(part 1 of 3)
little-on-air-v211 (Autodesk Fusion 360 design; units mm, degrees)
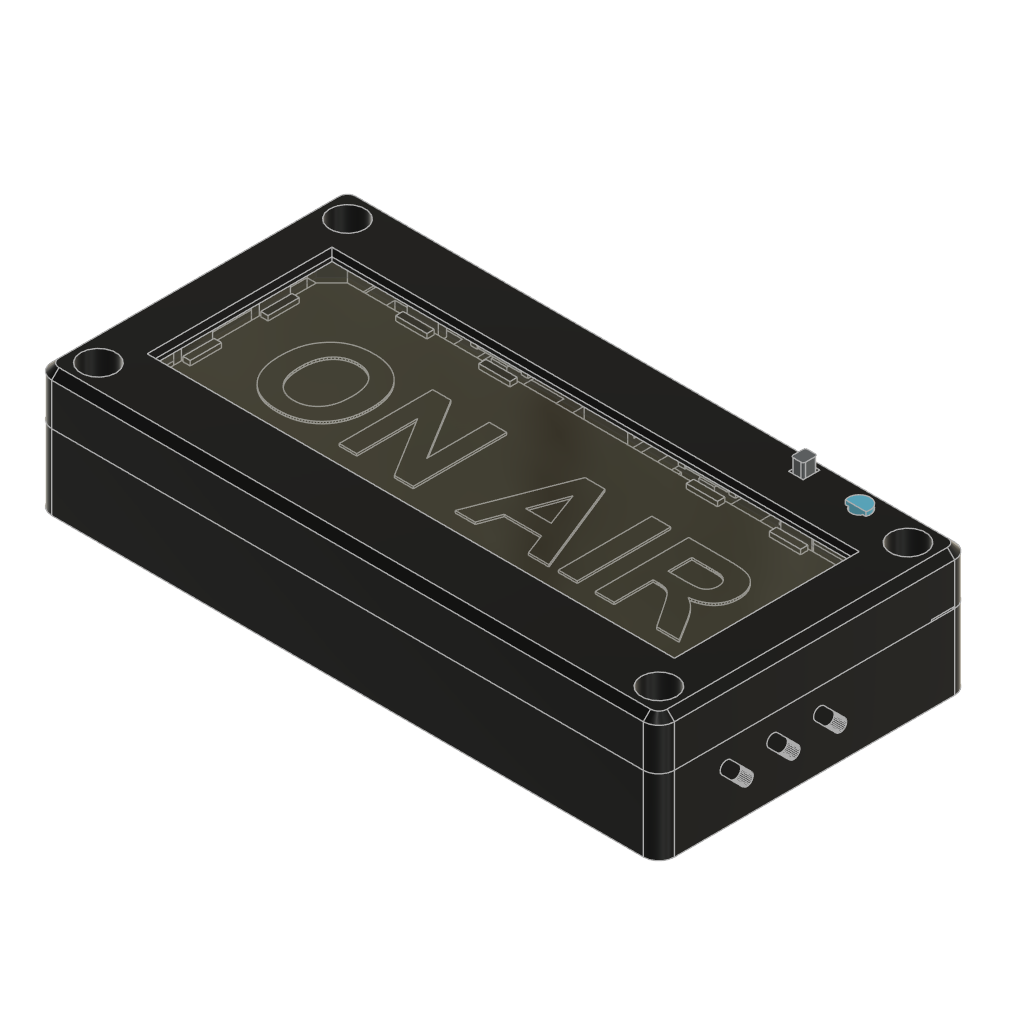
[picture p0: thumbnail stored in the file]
description: netfabb.mesh_body
description: Laser only; rear-engrave mirrored shared vector master
description: 1.6 mm black; 0.4 mm white letters; integral hidden spacer pads
description: Flat frame down, LED pads up; no electronics mounts
description: Optional 1.6 mm laminate only; omit with printed backing; print 0.1 mm layers
description: 8x8x2; emitter offset assumed 1 mm
description: Measured 28.1 x17.5; USB overhang 1.3; PCB thickness and USB section provisional
description: Measured body 10.6 x6 x5.05; flange 19.73; terminals 2.6
description: Measured 2.95 square, 5 high; 5.8 slot gives 2.85 mm travel
description: 9.1 x3.72 x3.36; 0.7 mm terminals, 1.85 mm clear gaps, symmetric rows
description: 1.5 square x1.87; full travel 2.4 mm
description: Measured 17.8 x21 x1.2; USB centered across width, 1.75 overhang
description: 24 mm total case; parallel PCB nests; back face on print bed
description: Flat PCB keeper; broad rails, short contact pads, keyed reset guide
description: 52 x21 x10, front clearance preserved; no wire bundles on pouch
description: Existing inline 680 uF; laid on its side, maximum 8 dia x11.5 body
description: Eight identical M3x8 button heads, maximum 5.7 diameter x1.65 height
description: Ordinary M3 nuts, 5.5 across flats x2.4 thick
parameter "case_w" = 120 comment "Front width"
parameter "case_h" = 60 comment "Front height"
parameter "case_d" = 24 comment "Rear wiring margin included"
parameter "wall" = 2.4 comment "Structural shell wall"
parameter "front_lip" = 1.6 comment "Front optical lip"
parameter "front_depth" = 9.5 comment "Main front/rear seam"
parameter "acrylic_t" = 3.175 comment "Nominal Amazon 1/8 inch; measure actual sheet"
parameter "panel_w" = 104 comment "Shared optical outline"
parameter "panel_h" = 38 comment "Shared optical outline"
parameter "air_gap" = 0.5 comment "Rear engraving to white letter tips"
parameter "backing_base" = 1.6 comment "Black printed base"
parameter "letter_relief" = 0.4 comment "White letters above black base"
parameter "tray_t" = 1.6 comment "Optical retainer thickness"
parameter "fit" = 0.25 comment "Nominal mating clearance per side"
parameter "m3_hole" = 3.6 comment "M3 clearance"
parameter "nut_af" = 6 comment "Ordinary M3 nut trap"
parameter "head_d" = 6.8 comment "M3 socket-head counterbore"
parameter "head_depth" = 3.2 comment "Front bearing plane"
parameter "led_w" = 8 comment "Separated LED module"
parameter "led_h" = 8 comment "Separated LED module"
parameter "led_t" = 2 comment "LED module thickness"
parameter "led_optical_offset" = 1 comment "Unmeasured emitter center from module front"
parameter "text_h" = 18 comment "Reference text height"
parameter "switch_w" = 9.1
parameter "switch_h" = 3.72
parameter "switch_t" = 3.36
parameter "switch_throw" = 2.4
parameter "actuator_w" = 1.5
parameter "actuator_d" = 1.5
parameter "actuator_h" = 1.87
parameter "reset_y" = 56 comment "Provisional XIAO reset center"
parameter "reset_depth" = 14.55 comment "Provisional XIAO reset center"
parameter "reset_tip_x" = 110.7 comment "v2.5 measured reset stack and exterior projection"
parameter "reset_stroke" = 0.4 comment "v2.5 measured reset stack and exterior projection"
parameter "spdt_body_length" = 10.6
parameter "spdt_body_depth" = 6
parameter "spdt_body_height" = 5.05
parameter "spdt_flange_length" = 19.73
parameter "spdt_knob_height" = 5
parameter "spdt_knob_envelope" = 2.95
parameter "spdt_travel" = 2.85
parameter "spdt_fit_clearance" = 0.2
parameter "charger_pcb_width" = 17.5 comment "v2.3 measured fit revision; see change record"
parameter "charger_pcb_length" = 28.1 comment "v2.3 measured fit revision; see change record"
parameter "charger_usb_overhang" = 1.25 comment "v2.3 measured fit revision; see change record"
parameter "charger_fit_per_side" = 0.3 comment "v2.3 measured fit revision; see change record"
parameter "reset_guide_length" = 4 comment "v2.3 measured fit revision; see change record"
parameter "reset_guide_per_side" = 0.2 comment "v2.3 measured fit revision; see change record"
parameter "xiao_shift_side" = -0.2 comment "v2.3 measured fit revision; see change record"
parameter "xiao_shift_top" = 1.3 comment "v2.3 measured fit revision; see change record"
parameter "dpdt_actuator_exposed" = 0.72 comment "v2.3 measured fit revision; see change record"
parameter "charger_usb_width" = 8.85 comment "User measured September 10, 2026"
parameter "charger_usb_height" = 3.1 comment "User measured September 10, 2026"
parameter "xiao_usb_width" = 8.97 comment "User measured September 10, 2026"
parameter "xiao_usb_height" = 3.17 comment "User measured September 10, 2026"
parameter "xiao_usb_overhang" = 1.75 comment "User measured September 10, 2026"
parameter "dpdt_fit_per_side" = 0.35 comment "v2.4 second physical-fit revision"
parameter "yoke_main_thickness" = 2.75 comment "v2.4 second physical-fit revision"
parameter "side_vent_length" = 8 comment "v2.4 second physical-fit revision"
parameter "side_vent_width" = 2.4 comment "v2.4 second physical-fit revision"
parameter "xiao_pcb_thickness" = 1.2 comment "v2.5 measured physical fit"
parameter "xiao_usb_edge_margin" = 4.415 comment "v2.5 measured physical fit"
parameter "xiao_usb_front_depth" = 15.965 comment "v2.5 measured physical fit"
parameter "dpdt_terminal_width" = 0.7 comment "v2.5 measured physical fit"
parameter "dpdt_terminal_clear_gap" = 1.85 comment "v2.5 measured physical fit"
parameter "charger_lower_support_from_end" = 5 comment "v2.5 measured physical fit"
parameter "reset_free_play" = 0.1 comment "v2.5 measured reset stack"
parameter "reset_exterior_projection" = 3 comment "v2.5 measured reset stack"
parameter "reset_target_from_pcb_back" = 1.8 comment "v2.5 measured reset stack"
parameter "yoke_front_depth" = 9.65 comment "v2.5 common flat print face; no support for POWER roof"
parameter "yoke_screw_seat_thickness" = 1.75 comment "v2.5 common flat print face; no support for POWER roof"
parameter "common_screw_length" = 8 comment "v2.6 service revision"
parameter "closure_head_bearing" = 6.6 comment "v2.6 service revision"
parameter "closure_nut_front" = 11.5 comment "v2.6 service revision"
parameter "xiao_inward_shift" = 2 comment "v2.6 service revision"
parameter "xiao_rgb_y" = 55.006 comment "v2.6 service revision"
parameter "xiao_rgb_depth" = 26.155 comment "v2.6 service revision"
parameter "dpdt_pocket_width" = 9.5 comment "v2.6 service revision"
parameter "dpdt_retained_gap" = 0.15 comment "v2.6 service revision"
parameter "closure_nut_roof" = 2 comment "v2.6 full-depth common screw nut roof"
parameter "xiao_flat_pcb_back" = 19.7 comment "v2.7 measured component layout"
parameter "charger_flat_pcb_back" = 15.3 comment "v2.7 measured component layout"
parameter "reset_front_freeplay" = 0.25 comment "v2.7 measured component layout"
parameter "reset_front_stroke" = 0.8 comment "v2.7 measured component layout"
parameter "reset_front_projection" = 2.5 comment "v2.7 measured component layout"
parameter "indicator_guide_diameter" = 3.05
parameter "front_outer_bevel" = 1.4 comment "Equal-distance 45 degree cosmetic front chamfer"
parameter "front_opening_bevel" = 0.8 comment "Equal-distance 45 degree cosmetic front chamfer"
base_feature "Base Feature1" bodies "Body1"
base_feature "Base Feature1" bodies "Body1"
base_feature "Base Feature1"
base_feature "Base Feature1" bodies "Body1"
base_feature "Base Feature1" bodies "Body1"
base_feature "Base Feature1" bodies "Body1"
base_feature "Base Feature1" bodies "LED module", "LED module (1)", "LED module (2)", "LED module (3)"
base_feature "Base Feature1" bodies "Charger PCB", "Charger IC envelope", "Measured USB-C socket envelope"
base_feature "Base Feature1" bodies "SPDT main body"
base_feature "Base Feature1" bodies "SPDT lever"
base_feature "Base Feature1" bodies "Measured DPDT body"
base_feature "Base Feature1" bodies "Direct MODE actuator"
base_feature "Base Feature1" bodies "XIAO PCB", "XIAO component envelope", "Measured centered USB-C socket"
move "Move1"
move "Move1"
move "Move1"
move "Move1"
move "Move1"
move "Move1"
sketch "Close obsolete upper-right screw opening profile" plane through (0, 0, 0) normal (0, 0, 1) x axis (1, 0, 0)
  circle C1 centre (96, 54) radius 3.405
  dimension "d86" diameter C1 = 6.81
extrude "Extrude1" new body sketch "Close obsolete upper-right screw opening profile" against normal blind 9.5 bodies "Close obsolete upper-right screw opening"
combine "Combine1" bodies "Close obsolete upper-right screw opening"
work_plane "WorkPlane1" AlongDistance -1.6 ExtraOffset 0
sketch "Remove obsolete inboard compression seat profile" plane through (0, 0, -1.6) normal (0, 0, 1) x axis (1, 0, 0)
  line L1 (100.21, 49.79) -> (91.79, 49.79)
  line L2 (100.21, 57.6) -> (100.21, 49.79)
  line L3 (91.79, 57.6) -> (100.21, 57.6)
  line L4 (91.79, 49.79) -> (91.79, 57.6)
  point P2 (91.79, 49.79)
  point P3 (100.21, 49.79)
  point P4 (100.21, 57.6)
  dimension "d91" distance P2 P3 = 8.42
  dimension "d92" distance P3 P4 = 7.81
extrude "Extrude2" cut sketch "Remove obsolete inboard compression seat profile" against normal blind 7.91
work_plane "WorkPlane2" AlongDistance -1.5 ExtraOffset 0
sketch "New upper-right corner compression seat profile" plane through (0, 0, -1.5) normal (0, 0, 1) x axis (1, 0, 0)
  line L1 (118.2, 49.8) -> (109.8, 49.8)
  line L2 (118.2, 58.2) -> (118.2, 49.8)
  line L3 (109.8, 58.2) -> (118.2, 58.2)
  line L4 (109.8, 49.8) -> (109.8, 58.2)
  point P2 (109.8, 49.8)
  point P3 (118.2, 49.8)
  point P4 (118.2, 58.2)
  dimension "d97" distance P2 P3 = 8.4
  dimension "d98" distance P3 P4 = 8.4
extrude "Extrude3" new body sketch "New upper-right corner compression seat profile" against normal blind 8 bodies "New upper-right corner compression seat"
combine "Combine2" bodies "New upper-right corner compression seat"
work_plane "WorkPlane3" AlongDistance 0.02 ExtraOffset 0
sketch "New common M3 clearance profile" plane through (0, 0, 0.02) normal (0, 0, 1) x axis (1, 0, 0)
  circle C1 centre (114, 54) radius 1.8
  dimension "d103" diameter C1 = 3.6
extrude "Extrude4" cut sketch "New common M3 clearance profile" against normal blind 9.54
work_plane "WorkPlane4" AlongDistance 0.02 ExtraOffset 0
sketch "New common inset head bearing profile" plane through (0, 0, 0.02) normal (0, 0, 1) x axis (1, 0, 0)
  circle C1 centre (114, 54) radius 3.4
  dimension "d108" diameter C1 = 6.8
extrude "Extrude5" cut sketch "New common inset head bearing profile" against normal blind 6.62
work_plane "WorkPlane5" AlongDistance -1.5 ExtraOffset 0
sketch "Front reset guide broad collar profile" plane through (0, 0, -1.5) normal (0, 0, 1) x axis (1, 0, 0)
  line L1 (95.515, 52.6) -> (88.515, 52.6)
  line L2 (95.515, 59.4) -> (95.515, 52.6)
  line L3 (88.515, 59.4) -> (95.515, 59.4)
  line L4 (88.515, 52.6) -> (88.515, 59.4)
  point P2 (88.515, 52.6)
  point P3 (95.515, 52.6)
  point P4 (95.515, 59.4)
  dimension "d113" distance P2 P3 = 7
  dimension "d114" distance P3 P4 = 6.8
extrude "Extrude6" new body sketch "Front reset guide broad collar profile" against normal blind 4.5 bodies "Front reset guide broad collar"
combine "Combine3" bodies "Front reset guide broad collar"
work_plane "WorkPlane6" AlongDistance 0.1 ExtraOffset 0
sketch "Front keyed reset running guide profile" plane through (0, 0, 0.1) normal (0, 0, 1) x axis (1, 0, 0)
  line L1 (93.415, 54.4) -> (90.615, 54.4)
  line L2 (93.415, 57.6) -> (93.415, 54.4)
  line L3 (90.615, 57.6) -> (93.415, 57.6)
  line L4 (90.615, 54.4) -> (90.615, 57.6)
  point P2 (90.615, 54.4)
  point P3 (93.415, 54.4)
  point P4 (93.415, 57.6)
  dimension "d119" distance P2 P3 = 2.8
  dimension "d120" distance P3 P4 = 3.2
extrude "Extrude7" cut sketch "Front keyed reset running guide profile" against normal blind 6.2
work_plane "WorkPlane7" AlongDistance -6 ExtraOffset 0
sketch "Reset captive flange loading pocket profile" plane through (0, 0, -6) normal (0, 0, 1) x axis (1, 0, 0)
  line L1 (94.915, 53.1) -> (89.115, 53.1)
  line L2 (94.915, 58.9) -> (94.915, 53.1)
  line L3 (89.115, 58.9) -> (94.915, 58.9)
  line L4 (89.115, 53.1) -> (89.115, 58.9)
  point P2 (89.115, 53.1)
  point P3 (94.915, 53.1)
  point P4 (94.915, 58.9)
  dimension "d125" distance P2 P3 = 5.8
  dimension "d126" distance P3 P4 = 5.8
extrude "Extrude8" cut sketch "Reset captive flange loading pocket profile" against normal blind 3.51
work_plane "WorkPlane8" AlongDistance 0.02 ExtraOffset 0
sketch "RGB6 front indicator aperture profile" plane through (0, 0, 0.02) normal (0, 0, 1) x axis (1, 0, 0)
  circle C1 centre (103.605, 55.006) radius 1.6
  dimension "d131" diameter C1 = 3.2
extrude "Extrude9" cut sketch "RGB6 front indicator aperture profile" + "Front reset guide broad collar profile" profile of S1:C1 blind -9.55
work_plane "WorkPlane1" AlongDistance -9.5 ExtraOffset 0
sketch "Slim rear envelope profile" plane through (0, 0, -9.5) normal (0, 0, 1) x axis (1, 0, 0)
  line L1 (117, 0) -> (3, 0)
  line L2 (120, 57) -> (120, 3)
  line L3 (3, 60) -> (117, 60)
  line L4 (0, 3) -> (0, 57)
  arc A1 centre (117, 3) radius 3 clockwise from (120, 3) to (117, 0)
  arc A2 centre (117, 57) radius 3 clockwise from (117, 60) to (120, 57)
  arc A3 centre (3, 57) radius 3 clockwise from (0, 57) to (3, 60)
  arc A4 centre (3, 3) radius 3 clockwise from (3, 0) to (0, 3)
extrude "Extrude1" new body sketch "Slim rear envelope profile" against normal blind 14.5
work_plane "WorkPlane2" AlongDistance -9.48 ExtraOffset 0
sketch "Open electronics cavity profile" plane through (0, 0, -9.48) normal (0, 0, 1) x axis (1, 0, 0)
  line L1 (117.6, 2.4) -> (2.4, 2.4)
  line L2 (117.6, 57.6) -> (117.6, 2.4)
  line L3 (2.4, 57.6) -> (117.6, 57.6)
  line L4 (2.4, 2.4) -> (2.4, 57.6)
  point P2 (2.4, 2.4)
  point P3 (117.6, 2.4)
  point P4 (117.6, 57.6)
  dimension "d140" distance P2 P3 = 115.2
  dimension "d141" distance P3 P4 = 55.2
extrude "Extrude2" cut sketch "Open electronics cavity profile" against normal blind 12.22
work_plane "WorkPlane3" AlongDistance -9.5 ExtraOffset 0
sketch "Closure boss profile" plane through (0, 0, -9.5) normal (0, 0, 1) x axis (1, 0, 0)
  line L1 (10.2, 1.8) -> (1.8, 1.8)
  line L2 (10.2, 10.2) -> (10.2, 1.8)
  line L3 (1.8, 10.2) -> (10.2, 10.2)
  line L4 (1.8, 1.8) -> (1.8, 10.2)
  point P2 (1.8, 1.8)
  point P3 (10.2, 1.8)
  point P4 (10.2, 10.2)
  dimension "d146" distance P2 P3 = 8.4
  dimension "d147" distance P3 P4 = 8.4
extrude "Extrude3" new body sketch "Closure boss profile" against normal blind 12.2 bodies "Closure boss"
combine "Combine1" bodies "Closure boss"
work_plane "WorkPlane4" AlongDistance -11.5 ExtraOffset 0
sketch "Closure boss nut flats" plane through (0, 0, -11.5) normal (0, 0, 1) x axis (1, 0, 0)
  line L1 (7.7321, 9) -> (9.4641, 6)
  line L2 (4.2679, 9) -> (7.7321, 9)
  line L3 (2.5359, 6) -> (4.2679, 9)
  line L4 (4.2679, 3) -> (2.5359, 6)
  line L5 (7.7321, 3) -> (4.2679, 3)
  line L6 (9.4641, 6) -> (7.7321, 3)
extrude "Extrude4" cut sketch "Closure boss nut flats" against normal blind 3
work_plane "WorkPlane5" AlongDistance -11.5 ExtraOffset 0
sketch "Closure boss inward nut mouth profile" plane through (0, 0, -11.5) normal (0, 0, 1) x axis (1, 0, 0)
  line L1 (10.5, 3) -> (6, 3)
  line L2 (10.5, 9) -> (10.5, 3)
  line L3 (6, 9) -> (10.5, 9)
  line L4 (6, 3) -> (6, 9)
  point P2 (6, 3)
  point P3 (10.5, 3)
  point P4 (10.5, 9)
  dimension "d156" distance P2 P3 = 4.5
  dimension "d157" distance P3 P4 = 6
extrude "Extrude5" cut sketch "Closure boss inward nut mouth profile" against normal blind 3
work_plane "WorkPlane6" AlongDistance -9.48 ExtraOffset 0
sketch "Closure boss blind M3 clearance profile" plane through (0, 0, -9.48) normal (0, 0, 1) x axis (1, 0, 0)
  circle C1 centre (6, 6) radius 1.8
  dimension "d162" diameter C1 = 3.6
extrude "Extrude6" cut sketch "Closure boss blind M3 clearance profile" against normal blind 5.72
work_plane "WorkPlane7" AlongDistance -9.5 ExtraOffset 0
sketch "Closure boss profile (1)" plane through (0, 0, -9.5) normal (0, 0, 1) x axis (1, 0, 0)
  line L1 (118.2, 1.8) -> (109.8, 1.8)
  line L2 (118.2, 10.2) -> (118.2, 1.8)
  line L3 (109.8, 10.2) -> (118.2, 10.2)
  line L4 (109.8, 1.8) -> (109.8, 10.2)
  point P2 (109.8, 1.8)
  point P3 (118.2, 1.8)
  point P4 (118.2, 10.2)
  dimension "d167" distance P2 P3 = 8.4
  dimension "d168" distance P3 P4 = 8.4
extrude "Extrude7" new body sketch "Closure boss profile (1)" against normal blind 12.2 bodies "Closure boss"
combine "Combine2" bodies "Closure boss"
work_plane "WorkPlane8" AlongDistance -11.5 ExtraOffset 0
sketch "Closure boss nut flats (1)" plane through (0, 0, -11.5) normal (0, 0, 1) x axis (1, 0, 0)
  line L1 (115.7321, 9) -> (117.4641, 6)
  line L2 (112.2679, 9) -> (115.7321, 9)
  line L3 (110.5359, 6) -> (112.2679, 9)
  line L4 (112.2679, 3) -> (110.5359, 6)
  line L5 (115.7321, 3) -> (112.2679, 3)
  line L6 (117.4641, 6) -> (115.7321, 3)
extrude "Extrude8" cut sketch "Closure boss nut flats (1)" against normal blind 3
work_plane "WorkPlane9" AlongDistance -11.5 ExtraOffset 0
sketch "Closure boss inward nut mouth profile (1)" plane through (0, 0, -11.5) normal (0, 0, 1) x axis (1, 0, 0)
  line L1 (114, 3) -> (109.5, 3)
  line L2 (114, 9) -> (114, 3)
  line L3 (109.5, 9) -> (114, 9)
  line L4 (109.5, 3) -> (109.5, 9)
  point P2 (109.5, 3)
  point P3 (114, 3)
  point P4 (114, 9)
  dimension "d177" distance P2 P3 = 4.5
  dimension "d178" distance P3 P4 = 6
extrude "Extrude9" cut sketch "Closure boss inward nut mouth profile (1)" against normal blind 3
work_plane "WorkPlane10" AlongDistance -9.48 ExtraOffset 0
sketch "Closure boss blind M3 clearance profile (1)" plane through (0, 0, -9.48) normal (0, 0, 1) x axis (1, 0, 0)
  circle C1 centre (114, 6) radius 1.8
  dimension "d183" diameter C1 = 3.6
extrude "Extrude10" cut sketch "Closure boss blind M3 clearance profile (1)" against normal blind 5.72
work_plane "WorkPlane11" AlongDistance -9.5 ExtraOffset 0
sketch "Closure boss profile (2)" plane through (0, 0, -9.5) normal (0, 0, 1) x axis (1, 0, 0)
  line L1 (10.2, 49.8) -> (1.8, 49.8)
  line L2 (10.2, 58.2) -> (10.2, 49.8)
  line L3 (1.8, 58.2) -> (10.2, 58.2)
  line L4 (1.8, 49.8) -> (1.8, 58.2)
  point P2 (1.8, 49.8)
  point P3 (10.2, 49.8)
  point P4 (10.2, 58.2)
  dimension "d188" distance P2 P3 = 8.4
  dimension "d189" distance P3 P4 = 8.4
extrude "Extrude11" new body sketch "Closure boss profile (2)" against normal blind 12.2 bodies "Closure boss"
combine "Combine3" bodies "Closure boss"
work_plane "WorkPlane12" AlongDistance -11.5 ExtraOffset 0
sketch "Closure boss nut flats (2)" plane through (0, 0, -11.5) normal (0, 0, 1) x axis (1, 0, 0)
  line L1 (3, 55.7321) -> (6, 57.4641)
  line L2 (3, 52.2679) -> (3, 55.7321)
  line L3 (6, 50.5359) -> (3, 52.2679)
  line L4 (9, 52.2679) -> (6, 50.5359)
  line L5 (9, 55.7321) -> (9, 52.2679)
  line L6 (6, 57.4641) -> (9, 55.7321)
extrude "Extrude12" cut sketch "Closure boss nut flats (2)" against normal blind 3
work_plane "WorkPlane13" AlongDistance -11.5 ExtraOffset 0
sketch "Closure boss inward nut mouth profile (2)" plane through (0, 0, -11.5) normal (0, 0, 1) x axis (1, 0, 0)
  line L1 (9, 49.5) -> (3, 49.5)
  line L2 (9, 54) -> (9, 49.5)
  line L3 (3, 54) -> (9, 54)
  line L4 (3, 49.5) -> (3, 54)
  point P2 (3, 49.5)
  point P3 (9, 49.5)
  point P4 (9, 54)
  dimension "d198" distance P2 P3 = 6
  dimension "d199" distance P3 P4 = 4.5
extrude "Extrude13" cut sketch "Closure boss inward nut mouth profile (2)" against normal blind 3
work_plane "WorkPlane14" AlongDistance -9.48 ExtraOffset 0
sketch "Closure boss blind M3 clearance profile (2)" plane through (0, 0, -9.48) normal (0, 0, 1) x axis (1, 0, 0)
  circle C1 centre (6, 54) radius 1.8
  dimension "d204" diameter C1 = 3.6
extrude "Extrude14" cut sketch "Closure boss blind M3 clearance profile (2)" against normal blind 5.72
work_plane "WorkPlane15" AlongDistance -9.5 ExtraOffset 0
sketch "Closure boss profile (3)" plane through (0, 0, -9.5) normal (0, 0, 1) x axis (1, 0, 0)
  line L1 (118.2, 49.8) -> (109.8, 49.8)
  line L2 (118.2, 58.2) -> (118.2, 49.8)
  line L3 (109.8, 58.2) -> (118.2, 58.2)
  line L4 (109.8, 49.8) -> (109.8, 58.2)
  point P2 (109.8, 49.8)
  point P3 (118.2, 49.8)
  point P4 (118.2, 58.2)
  dimension "d209" distance P2 P3 = 8.4
  dimension "d210" distance P3 P4 = 8.4
extrude "Extrude15" new body sketch "Closure boss profile (3)" against normal blind 12.2 bodies "Closure boss"
combine "Combine4" bodies "Closure boss"
work_plane "WorkPlane16" AlongDistance -11.5 ExtraOffset 0
sketch "Closure boss nut flats (3)" plane through (0, 0, -11.5) normal (0, 0, 1) x axis (1, 0, 0)
  line L1 (115.7321, 57) -> (117.4641, 54)
  line L2 (112.2679, 57) -> (115.7321, 57)
  line L3 (110.5359, 54) -> (112.2679, 57)
  line L4 (112.2679, 51) -> (110.5359, 54)
  line L5 (115.7321, 51) -> (112.2679, 51)
  line L6 (117.4641, 54) -> (115.7321, 51)
extrude "Extrude16" cut sketch "Closure boss nut flats (3)" against normal blind 3
work_plane "WorkPlane17" AlongDistance -11.5 ExtraOffset 0
sketch "Closure boss inward nut mouth profile (3)" plane through (0, 0, -11.5) normal (0, 0, 1) x axis (1, 0, 0)
  line L1 (114, 51) -> (109.5, 51)
  line L2 (114, 57) -> (114, 51)
  line L3 (109.5, 57) -> (114, 57)
  line L4 (109.5, 51) -> (109.5, 57)
  point P2 (109.5, 51)
  point P3 (114, 51)
  point P4 (114, 57)
  dimension "d219" distance P2 P3 = 4.5
  dimension "d220" distance P3 P4 = 6
extrude "Extrude17" cut sketch "Closure boss inward nut mouth profile (3)" against normal blind 3
work_plane "WorkPlane18" AlongDistance -9.48 ExtraOffset 0
sketch "Closure boss blind M3 clearance profile (3)" plane through (0, 0, -9.48) normal (0, 0, 1) x axis (1, 0, 0)
  circle C1 centre (114, 54) radius 1.8
  dimension "d225" diameter C1 = 3.6
extrude "Extrude18" cut sketch "Closure boss blind M3 clearance profile (3)" against normal blind 5.72
work_plane "WorkPlane19" AlongDistance -12.4 ExtraOffset 0
sketch "Keeper boss profile" plane through (0, 0, -12.4) normal (0, 0, 1) x axis (1, 0, 0)
  line L1 (39.2, 33.8) -> (30.8, 33.8)
  line L2 (39.2, 42.2) -> (39.2, 33.8)
  line L3 (30.8, 42.2) -> (39.2, 42.2)
  line L4 (30.8, 33.8) -> (30.8, 42.2)
  point P2 (30.8, 33.8)
  point P3 (39.2, 33.8)
  point P4 (39.2, 42.2)
  dimension "d230" distance P2 P3 = 8.4
  dimension "d231" distance P3 P4 = 8.4
extrude "Extrude19" new body sketch "Keeper boss profile" against normal blind 9.3 bodies "Keeper boss"
combine "Combine5" bodies "Keeper boss"
work_plane "WorkPlane20" AlongDistance -13.8 ExtraOffset 0
sketch "Keeper boss nut flats" plane through (0, 0, -13.8) normal (0, 0, 1) x axis (1, 0, 0)
  line L1 (36.7321, 41) -> (38.4641, 38)
  line L2 (33.2679, 41) -> (36.7321, 41)
  line L3 (31.5359, 38) -> (33.2679, 41)
  line L4 (33.2679, 35) -> (31.5359, 38)
  line L5 (36.7321, 35) -> (33.2679, 35)
  line L6 (38.4641, 38) -> (36.7321, 35)
extrude "Extrude20" cut sketch "Keeper boss nut flats" against normal blind 3
work_plane "WorkPlane21" AlongDistance -13.8 ExtraOffset 0
sketch "Keeper boss inward nut mouth profile" plane through (0, 0, -13.8) normal (0, 0, 1) x axis (1, 0, 0)
  line L1 (39.5, 35) -> (35, 35)
  line L2 (39.5, 41) -> (39.5, 35)
  line L3 (35, 41) -> (39.5, 41)
  line L4 (35, 35) -> (35, 41)
  point P2 (35, 35)
  point P3 (39.5, 35)
  point P4 (39.5, 41)
  dimension "d240" distance P2 P3 = 4.5
  dimension "d241" distance P3 P4 = 6
extrude "Extrude21" cut sketch "Keeper boss inward nut mouth profile" against normal blind 3
work_plane "WorkPlane22" AlongDistance -12.38 ExtraOffset 0
sketch "Keeper boss blind M3 clearance profile" plane through (0, 0, -12.38) normal (0, 0, 1) x axis (1, 0, 0)
  circle C1 centre (35, 38) radius 1.8
  dimension "d246" diameter C1 = 3.6
extrude "Extrude22" cut sketch "Keeper boss blind M3 clearance profile" against normal blind 5.82
work_plane "WorkPlane23" AlongDistance -12.4 ExtraOffset 0
sketch "Keeper boss profile (1)" plane through (0, 0, -12.4) normal (0, 0, 1) x axis (1, 0, 0)
  line L1 (77.2, 33.8) -> (68.8, 33.8)
  line L2 (77.2, 42.2) -> (77.2, 33.8)
  line L3 (68.8, 42.2) -> (77.2, 42.2)
  line L4 (68.8, 33.8) -> (68.8, 42.2)
  point P2 (68.8, 33.8)
  point P3 (77.2, 33.8)
  point P4 (77.2, 42.2)
  dimension "d251" distance P2 P3 = 8.4
  dimension "d252" distance P3 P4 = 8.4
extrude "Extrude23" new body sketch "Keeper boss profile (1)" against normal blind 9.3 bodies "Keeper boss"
combine "Combine6" bodies "Keeper boss"
work_plane "WorkPlane24" AlongDistance -13.8 ExtraOffset 0
sketch "Keeper boss nut flats (1)" plane through (0, 0, -13.8) normal (0, 0, 1) x axis (1, 0, 0)
  line L1 (74.7321, 41) -> (76.4641, 38)
  line L2 (71.2679, 41) -> (74.7321, 41)
  line L3 (69.5359, 38) -> (71.2679, 41)
  line L4 (71.2679, 35) -> (69.5359, 38)
  line L5 (74.7321, 35) -> (71.2679, 35)
  line L6 (76.4641, 38) -> (74.7321, 35)
extrude "Extrude24" cut sketch "Keeper boss nut flats (1)" against normal blind 3
work_plane "WorkPlane25" AlongDistance -13.8 ExtraOffset 0
sketch "Keeper boss inward nut mouth profile (1)" plane through (0, 0, -13.8) normal (0, 0, 1) x axis (1, 0, 0)
  line L1 (73, 35) -> (68.5, 35)
  line L2 (73, 41) -> (73, 35)
  line L3 (68.5, 41) -> (73, 41)
  line L4 (68.5, 35) -> (68.5, 41)
  point P2 (68.5, 35)
  point P3 (73, 35)
  point P4 (73, 41)
  dimension "d261" distance P2 P3 = 4.5
  dimension "d262" distance P3 P4 = 6
extrude "Extrude25" cut sketch "Keeper boss inward nut mouth profile (1)" against normal blind 3
work_plane "WorkPlane26" AlongDistance -12.38 ExtraOffset 0
sketch "Keeper boss blind M3 clearance profile (1)" plane through (0, 0, -12.38) normal (0, 0, 1) x axis (1, 0, 0)
  circle C1 centre (73, 38) radius 1.8
  dimension "d267" diameter C1 = 3.6
extrude "Extrude26" cut sketch "Keeper boss blind M3 clearance profile (1)" against normal blind 5.82
work_plane "WorkPlane27" AlongDistance -18 ExtraOffset 0
sketch "Battery low fence profile" plane through (0, 0, -18) normal (0, 0, 1) x axis (1, 0, 0)
  line L1 (89.6, 8.4) -> (32.4, 8.4)
  line L2 (89.6, 10) -> (89.6, 8.4)
  line L3 (32.4, 10) -> (89.6, 10)
  line L4 (32.4, 8.4) -> (32.4, 10)
  point P2 (32.4, 8.4)
  point P3 (89.6, 8.4)
  point P4 (89.6, 10)
  dimension "d272" distance P2 P3 = 57.2
  dimension "d273" distance P3 P4 = 1.6
extrude "Extrude27" new body sketch "Battery low fence profile" against normal blind 3.7 bodies "Battery low fence"
work_plane "WorkPlane28" AlongDistance -18 ExtraOffset 0
sketch "Battery low fence profile (1)" plane through (0, 0, -18) normal (0, 0, 1) x axis (1, 0, 0)
  line L1 (34, 10) -> (32.4, 10)
  line L2 (34, 33) -> (34, 10)
  line L3 (32.4, 33) -> (34, 33)
  line L4 (32.4, 10) -> (32.4, 33)
  point P2 (32.4, 10)
  point P3 (34, 10)
  point P4 (34, 33)
  dimension "d278" distance P2 P3 = 1.6
  dimension "d279" distance P3 P4 = 23
extrude "Extrude28" new body sketch "Battery low fence profile (1)" against normal blind 3.7 bodies "Battery low fence (1)"
work_plane "WorkPlane29" AlongDistance -18 ExtraOffset 0
sketch "Battery low fence profile (2)" plane through (0, 0, -18) normal (0, 0, 1) x axis (1, 0, 0)
  line L1 (89.6, 10) -> (88, 10)
  line L2 (89.6, 27) -> (89.6, 10)
  line L3 (88, 27) -> (89.6, 27)
  line L4 (88, 10) -> (88, 27)
  point P2 (88, 10)
  point P3 (89.6, 10)
  point P4 (89.6, 27)
  dimension "d284" distance P2 P3 = 1.6
  dimension "d285" distance P3 P4 = 17
extrude "Extrude29" new body sketch "Battery low fence profile (2)" against normal blind 3.7 bodies "Battery low fence (2)"
work_plane "WorkPlane30" AlongDistance -18 ExtraOffset 0
sketch "Battery low fence profile (3)" plane through (0, 0, -18) normal (0, 0, 1) x axis (1, 0, 0)
  line L1 (74, 33) -> (32.4, 33)
  line L2 (74, 34.6) -> (74, 33)
  line L3 (32.4, 34.6) -> (74, 34.6)
  line L4 (32.4, 33) -> (32.4, 34.6)
  point P2 (32.4, 33)
  point P3 (74, 33)
  point P4 (74, 34.6)
  dimension "d290" distance P2 P3 = 41.6
  dimension "d291" distance P3 P4 = 1.6
extrude "Extrude30" new body sketch "Battery low fence profile (3)" against normal blind 3.7 bodies "Battery low fence (3)"
work_plane "WorkPlane31" AlongDistance -21.4 ExtraOffset 0
sketch "Battery insulated bed profile" plane through (0, 0, -21.4) normal (0, 0, 1) x axis (1, 0, 0)
  line L1 (88, 10) -> (34, 10)
  line L2 (88, 33) -> (88, 10)
  line L3 (34, 33) -> (88, 33)
  line L4 (34, 10) -> (34, 33)
  point P2 (34, 10)
  point P3 (88, 10)
  point P4 (88, 33)
  dimension "d296" distance P2 P3 = 54
  dimension "d297" distance P3 P4 = 23
extrude "Extrude31" new body sketch "Battery insulated bed profile" against normal blind 0.3 bodies "Battery insulated bed"
work_plane "WorkPlane32" AlongDistance -17 ExtraOffset 0
sketch "Strap lug profile" plane through (0, 0, -17) normal (0, 0, 1) x axis (1, 0, 0)
  line L1 (32.4, 18) -> (28.4, 18)
  line L2 (32.4, 25) -> (32.4, 18)
  line L3 (28.4, 25) -> (32.4, 25)
  line L4 (28.4, 18) -> (28.4, 25)
  point P2 (28.4, 18)
  point P3 (32.4, 18)
  point P4 (32.4, 25)
  dimension "d302" distance P2 P3 = 4
  dimension "d303" distance P3 P4 = 7
extrude "Extrude32" new body sketch "Strap lug profile" against normal blind 4.7 bodies "Strap lug"
work_plane "WorkPlane33" AlongDistance -17 ExtraOffset 0
sketch "Strap lug profile (1)" plane through (0, 0, -17) normal (0, 0, 1) x axis (1, 0, 0)
  line L1 (94, 18) -> (90, 18)
  line L2 (94, 25) -> (94, 18)
  line L3 (90, 25) -> (94, 25)
  line L4 (90, 18) -> (90, 25)
  point P2 (90, 18)
  point P3 (94, 18)
  point P4 (94, 25)
  dimension "d308" distance P2 P3 = 4
  dimension "d309" distance P3 P4 = 7
extrude "Extrude33" new body sketch "Strap lug profile (1)" against normal blind 4.7 bodies "Strap lug (1)"
work_plane "WorkPlane34" AlongDistance -16.3 ExtraOffset 0
sketch "Charger clear-area PCB seat profile" plane through (0, 0, -16.3) normal (0, 0, 1) x axis (1, 0, 0)
  line L1 (14.25, 34.3) -> (12.25, 34.3)
  line L2 (14.25, 36.3) -> (14.25, 34.3)
  line L3 (12.25, 36.3) -> (14.25, 36.3)
  line L4 (12.25, 34.3) -> (12.25, 36.3)
  point P2 (12.25, 34.3)
  point P3 (14.25, 34.3)
  point P4 (14.25, 36.3)
  dimension "d314" distance P2 P3 = 2
  dimension "d315" distance P3 P4 = 2
extrude "Extrude34" new body sketch "Charger clear-area PCB seat profile" against normal blind 5.4 bodies "Charger clear-area PCB seat"
work_plane "WorkPlane35" AlongDistance -16.3 ExtraOffset 0
sketch "Charger clear-area PCB seat profile (1)" plane through (0, 0, -16.3) normal (0, 0, 1) x axis (1, 0, 0)
  line L1 (14.25, 53.5) -> (12.25, 53.5)
  line L2 (14.25, 56.5) -> (14.25, 53.5)
  line L3 (12.25, 56.5) -> (14.25, 56.5)
  line L4 (12.25, 53.5) -> (12.25, 56.5)
  point P2 (12.25, 53.5)
  point P3 (14.25, 53.5)
  point P4 (14.25, 56.5)
  dimension "d320" distance P2 P3 = 2
  dimension "d321" distance P3 P4 = 3
extrude "Extrude35" new body sketch "Charger clear-area PCB seat profile (1)" against normal blind 5.4 bodies "Charger clear-area PCB seat (1)"
work_plane "WorkPlane36" AlongDistance -16.3 ExtraOffset 0
sketch "Charger clear-area PCB seat profile (2)" plane through (0, 0, -16.3) normal (0, 0, 1) x axis (1, 0, 0)
  line L1 (29.75, 34.3) -> (27.75, 34.3)
  line L2 (29.75, 36.3) -> (29.75, 34.3)
  line L3 (27.75, 36.3) -> (29.75, 36.3)
  line L4 (27.75, 34.3) -> (27.75, 36.3)
  point P2 (27.75, 34.3)
  point P3 (29.75, 34.3)
  point P4 (29.75, 36.3)
  dimension "d326" distance P2 P3 = 2
  dimension "d327" distance P3 P4 = 2
extrude "Extrude36" new body sketch "Charger clear-area PCB seat profile (2)" against normal blind 5.4 bodies "Charger clear-area PCB seat (2)"
work_plane "WorkPlane37" AlongDistance -16.3 ExtraOffset 0
sketch "Charger clear-area PCB seat profile (3)" plane through (0, 0, -16.3) normal (0, 0, 1) x axis (1, 0, 0)
  line L1 (29.75, 53.5) -> (27.75, 53.5)
  line L2 (29.75, 56.5) -> (29.75, 53.5)
  line L3 (27.75, 56.5) -> (29.75, 56.5)
  line L4 (27.75, 53.5) -> (27.75, 56.5)
  point P2 (27.75, 53.5)
  point P3 (29.75, 53.5)
  point P4 (29.75, 56.5)
  dimension "d332" distance P2 P3 = 2
  dimension "d333" distance P3 P4 = 3
extrude "Extrude37" new body sketch "Charger clear-area PCB seat profile (3)" against normal blind 5.4 bodies "Charger clear-area PCB seat (3)"
work_plane "WorkPlane38" AlongDistance -15 ExtraOffset 0
sketch "Charger side fence profile" plane through (0, 0, -15) normal (0, 0, 1) x axis (1, 0, 0)
  line L1 (11.95, 31) -> (10.05, 31)
  line L2 (11.95, 56) -> (11.95, 31)
  line L3 (10.05, 56) -> (11.95, 56)
  line L4 (10.05, 31) -> (10.05, 56)
  point P2 (10.05, 31)
  point P3 (11.95, 31)
  point P4 (11.95, 56)
  dimension "d338" distance P2 P3 = 1.9
  dimension "d339" distance P3 P4 = 25
extrude "Extrude38" new body sketch "Charger side fence profile" against normal blind 6.7 bodies "Charger side fence"
work_plane "WorkPlane39" AlongDistance -15 ExtraOffset 0
sketch "Charger side fence profile (1)" plane through (0, 0, -15) normal (0, 0, 1) x axis (1, 0, 0)
  line L1 (31.95, 31) -> (30.05, 31)
  line L2 (31.95, 56) -> (31.95, 31)
  line L3 (30.05, 56) -> (31.95, 56)
  line L4 (30.05, 31) -> (30.05, 56)
  point P2 (30.05, 31)
  point P3 (31.95, 31)
  point P4 (31.95, 56)
  dimension "d344" distance P2 P3 = 1.9
  dimension "d345" distance P3 P4 = 25
extrude "Extrude39" new body sketch "Charger side fence profile (1)" against normal blind 6.7 bodies "Charger side fence (1)"
work_plane "WorkPlane40" AlongDistance -15 ExtraOffset 0
sketch "Charger lower central stop profile" plane through (0, 0, -15) normal (0, 0, 1) x axis (1, 0, 0)
  line L1 (26, 28.1) -> (16, 28.1)
  line L2 (26, 30) -> (26, 28.1)
  line L3 (16, 30) -> (26, 30)
  line L4 (16, 28.1) -> (16, 30)
  point P2 (16, 28.1)
  point P3 (26, 28.1)
  point P4 (26, 30)
  dimension "d350" distance P2 P3 = 10
  dimension "d351" distance P3 P4 = 1.9
extrude "Extrude40" new body sketch "Charger lower central stop profile" against normal blind 6.7 bodies "Charger lower central stop"
work_plane "WorkPlane41" AlongDistance -15 ExtraOffset 0
sketch "Charger upper end stop profile" plane through (0, 0, -15) normal (0, 0, 1) x axis (1, 0, 0)
  line L1 (14.25, 58.65) -> (12.25, 58.65)
  line L2 (14.25, 59.75) -> (14.25, 58.65)
  line L3 (12.25, 59.75) -> (14.25, 59.75)
  line L4 (12.25, 58.65) -> (12.25, 59.75)
  point P2 (12.25, 58.65)
  point P3 (14.25, 58.65)
  point P4 (14.25, 59.75)
  dimension "d356" distance P2 P3 = 2
  dimension "d357" distance P3 P4 = 1.1
extrude "Extrude41" new body sketch "Charger upper end stop profile" against normal blind 6.7 bodies "Charger upper end stop"
work_plane "WorkPlane42" AlongDistance -15 ExtraOffset 0
sketch "Charger upper end stop profile (1)" plane through (0, 0, -15) normal (0, 0, 1) x axis (1, 0, 0)
  line L1 (29.75, 58.65) -> (27.75, 58.65)
  line L2 (29.75, 59.75) -> (29.75, 58.65)
  line L3 (27.75, 59.75) -> (29.75, 59.75)
  line L4 (27.75, 58.65) -> (27.75, 59.75)
  point P2 (27.75, 58.65)
  point P3 (29.75, 58.65)
  point P4 (29.75, 59.75)
  dimension "d362" distance P2 P3 = 2
  dimension "d363" distance P3 P4 = 1.1
extrude "Extrude42" new body sketch "Charger upper end stop profile (1)" against normal blind 6.7 bodies "Charger upper end stop (1)"
work_plane "WorkPlane43" AlongDistance -19.7 ExtraOffset 0
sketch "XIAO short-end PCB seat profile" plane through (0, 0, -19.7) normal (0, 0, 1) x axis (1, 0, 0)
  line L1 (91.25, 36.8) -> (89.25, 36.8)
  line L2 (91.25, 38.2) -> (91.25, 36.8)
  line L3 (89.25, 38.2) -> (91.25, 38.2)
  line L4 (89.25, 36.8) -> (89.25, 38.2)
  point P2 (89.25, 36.8)
  point P3 (91.25, 36.8)
  point P4 (91.25, 38.2)
  dimension "d368" distance P2 P3 = 2
  dimension "d369" distance P3 P4 = 1.4
extrude "Extrude43" new body sketch "XIAO short-end PCB seat profile" against normal blind 2 bodies "XIAO short-end PCB seat"
work_plane "WorkPlane44" AlongDistance -19.7 ExtraOffset 0
sketch "XIAO short-end PCB seat profile (1)" plane through (0, 0, -19.7) normal (0, 0, 1) x axis (1, 0, 0)
  line L1 (91.25, 56.65) -> (89.25, 56.65)
  line L2 (91.25, 57.8) -> (91.25, 56.65)
  line L3 (89.25, 57.8) -> (91.25, 57.8)
  line L4 (89.25, 56.65) -> (89.25, 57.8)
  point P2 (89.25, 56.65)
  point P3 (91.25, 56.65)
  point P4 (91.25, 57.8)
  dimension "d374" distance P2 P3 = 2
  dimension "d375" distance P3 P4 = 1.15
extrude "Extrude44" new body sketch "XIAO short-end PCB seat profile (1)" against normal blind 2 bodies "XIAO short-end PCB seat (1)"
work_plane "WorkPlane45" AlongDistance -19.7 ExtraOffset 0
sketch "XIAO short-end PCB seat profile (2)" plane through (0, 0, -19.7) normal (0, 0, 1) x axis (1, 0, 0)
  line L1 (106.55, 36.8) -> (104.55, 36.8)
  line L2 (106.55, 38.2) -> (106.55, 36.8)
  line L3 (104.55, 38.2) -> (106.55, 38.2)
  line L4 (104.55, 36.8) -> (104.55, 38.2)
  point P2 (104.55, 36.8)
  point P3 (106.55, 36.8)
  point P4 (106.55, 38.2)
  dimension "d380" distance P2 P3 = 2
  dimension "d381" distance P3 P4 = 1.4
extrude "Extrude45" new body sketch "XIAO short-end PCB seat profile (2)" against normal blind 2 bodies "XIAO short-end PCB seat (2)"
work_plane "WorkPlane46" AlongDistance -19.7 ExtraOffset 0
sketch "XIAO short-end PCB seat profile (3)" plane through (0, 0, -19.7) normal (0, 0, 1) x axis (1, 0, 0)
  line L1 (106.55, 56.65) -> (104.55, 56.65)
  line L2 (106.55, 57.8) -> (106.55, 56.65)
  line L3 (104.55, 57.8) -> (106.55, 57.8)
  line L4 (104.55, 56.65) -> (104.55, 57.8)
  point P2 (104.55, 56.65)
  point P3 (106.55, 56.65)
  point P4 (106.55, 57.8)
  dimension "d386" distance P2 P3 = 2
  dimension "d387" distance P3 P4 = 1.15
extrude "Extrude46" new body sketch "XIAO short-end PCB seat profile (3)" against normal blind 2 bodies "XIAO short-end PCB seat (3)"
work_plane "WorkPlane47" AlongDistance -19.7 ExtraOffset 0
sketch "XIAO reset reaction support profile" plane through (0, 0, -19.7) normal (0, 0, 1) x axis (1, 0, 0)
  line L1 (93.2, 54.8) -> (90.8, 54.8)
  line L2 (93.2, 57.2) -> (93.2, 54.8)
  line L3 (90.8, 57.2) -> (93.2, 57.2)
  line L4 (90.8, 54.8) -> (90.8, 57.2)
  point P2 (90.8, 54.8)
  point P3 (93.2, 54.8)
  point P4 (93.2, 57.2)
  dimension "d392" distance P2 P3 = 2.4
  dimension "d393" distance P3 P4 = 2.4
extrude "Extrude47" new body sketch "XIAO reset reaction support profile" against normal blind 2 bodies "XIAO reset reaction support"
work_plane "WorkPlane48" AlongDistance -18.25 ExtraOffset 0
sketch "XIAO bottom end stop profile" plane through (0, 0, -18.25) normal (0, 0, 1) x axis (1, 0, 0)
  line L1 (105, 34.7) -> (90, 34.7)
  line L2 (105, 36.55) -> (105, 34.7)
  line L3 (90, 36.55) -> (105, 36.55)
  line L4 (90, 34.7) -> (90, 36.55)
  point P2 (90, 34.7)
  point P3 (105, 34.7)
  point P4 (105, 36.55)
  dimension "d398" distance P2 P3 = 15
  dimension "d399" distance P3 P4 = 1.85
extrude "Extrude48" new body sketch "XIAO bottom end stop profile" against normal blind 3.45 bodies "XIAO bottom end stop"
work_plane "WorkPlane49" AlongDistance -18.25 ExtraOffset 0
sketch "XIAO upper end stop profile" plane through (0, 0, -18.25) normal (0, 0, 1) x axis (1, 0, 0)
  line L1 (92.6, 58.05) -> (89, 58.05)
  line L2 (92.6, 59.75) -> (92.6, 58.05)
  line L3 (89, 59.75) -> (92.6, 59.75)
  line L4 (89, 58.05) -> (89, 59.75)
  point P2 (89, 58.05)
  point P3 (92.6, 58.05)
  point P4 (92.6, 59.75)
  dimension "d404" distance P2 P3 = 3.6
  dimension "d405" distance P3 P4 = 1.7
extrude "Extrude49" new body sketch "XIAO upper end stop profile" against normal blind 3.45 bodies "XIAO upper end stop"
work_plane "WorkPlane50" AlongDistance -18.25 ExtraOffset 0
sketch "XIAO upper end stop profile (1)" plane through (0, 0, -18.25) normal (0, 0, 1) x axis (1, 0, 0)
  line L1 (106.8, 58.05) -> (103.2, 58.05)
  line L2 (106.8, 59.75) -> (106.8, 58.05)
  line L3 (103.2, 59.75) -> (106.8, 59.75)
  line L4 (103.2, 58.05) -> (103.2, 59.75)
  point P2 (103.2, 58.05)
  point P3 (106.8, 58.05)
  point P4 (106.8, 59.75)
  dimension "d410" distance P2 P3 = 3.6
  dimension "d411" distance P3 P4 = 1.7
extrude "Extrude50" new body sketch "XIAO upper end stop profile (1)" against normal blind 3.45 bodies "XIAO upper end stop (1)"
work_plane "WorkPlane51" AlongDistance -18.25 ExtraOffset 0
sketch "XIAO short corner lateral stop profile" plane through (0, 0, -18.25) normal (0, 0, 1) x axis (1, 0, 0)
  line L1 (88.75, 35.8) -> (86.75, 35.8)
  line L2 (88.75, 38.3) -> (88.75, 35.8)
  line L3 (86.75, 38.3) -> (88.75, 38.3)
  line L4 (86.75, 35.8) -> (86.75, 38.3)
  point P2 (86.75, 35.8)
  point P3 (88.75, 35.8)
  point P4 (88.75, 38.3)
  dimension "d416" distance P2 P3 = 2
  dimension "d417" distance P3 P4 = 2.5
extrude "Extrude51" new body sketch "XIAO short corner lateral stop profile" against normal blind 3.45 bodies "XIAO short corner lateral stop"
work_plane "WorkPlane52" AlongDistance -18.25 ExtraOffset 0
sketch "XIAO short corner lateral stop profile (1)" plane through (0, 0, -18.25) normal (0, 0, 1) x axis (1, 0, 0)
  line L1 (88.75, 56.4) -> (86.75, 56.4)
  line L2 (88.75, 58) -> (88.75, 56.4)
  line L3 (86.75, 58) -> (88.75, 58)
  line L4 (86.75, 56.4) -> (86.75, 58)
  point P2 (86.75, 56.4)
  point P3 (88.75, 56.4)
  point P4 (88.75, 58)
  dimension "d422" distance P2 P3 = 2
  dimension "d423" distance P3 P4 = 1.6
extrude "Extrude52" new body sketch "XIAO short corner lateral stop profile (1)" against normal blind 3.45 bodies "XIAO short corner lateral stop (1)"
work_plane "WorkPlane53" AlongDistance -18.25 ExtraOffset 0
sketch "XIAO short corner lateral stop profile (2)" plane through (0, 0, -18.25) normal (0, 0, 1) x axis (1, 0, 0)
  line L1 (109.05, 35.8) -> (107.05, 35.8)
  line L2 (109.05, 38.3) -> (109.05, 35.8)
  line L3 (107.05, 38.3) -> (109.05, 38.3)
  line L4 (107.05, 35.8) -> (107.05, 38.3)
  point P2 (107.05, 35.8)
  point P3 (109.05, 35.8)
  point P4 (109.05, 38.3)
  dimension "d428" distance P2 P3 = 2
  dimension "d429" distance P3 P4 = 2.5
extrude "Extrude53" new body sketch "XIAO short corner lateral stop profile (2)" against normal blind 3.45 bodies "XIAO short corner lateral stop (2)"
work_plane "WorkPlane54" AlongDistance -18.25 ExtraOffset 0
sketch "XIAO short corner lateral stop profile (3)" plane through (0, 0, -18.25) normal (0, 0, 1) x axis (1, 0, 0)
  line L1 (109.05, 56.4) -> (107.05, 56.4)
  line L2 (109.05, 58) -> (109.05, 56.4)
  line L3 (107.05, 58) -> (109.05, 58)
  line L4 (107.05, 56.4) -> (107.05, 58)
  point P2 (107.05, 56.4)
  point P3 (109.05, 56.4)
  point P4 (109.05, 58)
  dimension "d434" distance P2 P3 = 2
  dimension "d435" distance P3 P4 = 1.6
extrude "Extrude54" new body sketch "XIAO short corner lateral stop profile (3)" against normal blind 3.45 bodies "XIAO short corner lateral stop (3)"
work_plane "WorkPlane55" AlongDistance -13.8 ExtraOffset 0
sketch "POWER nest profile" plane through (0, 0, -13.8) normal (0, 0, 1) x axis (1, 0, 0)
  line L1 (51.1, 51.15) -> (30.9, 51.15)
  line L2 (51.1, 59.75) -> (51.1, 51.15)
  line L3 (30.9, 59.75) -> (51.1, 59.75)
  line L4 (30.9, 51.15) -> (30.9, 59.75)
  point P2 (30.9, 51.15)
  point P3 (51.1, 51.15)
  point P4 (51.1, 59.75)
  dimension "d440" distance P2 P3 = 20.2
  dimension "d441" distance P3 P4 = 8.6
extrude "Extrude55" new body sketch "POWER nest profile" against normal blind 7.9 bodies "POWER nest"
work_plane "WorkPlane56" AlongDistance -13.7 ExtraOffset 0
sketch "MODE nest profile" plane through (0, 0, -13.7) normal (0, 0, 1) x axis (1, 0, 0)
  line L1 (66.75, 53.65) -> (53.25, 53.65)
  line L2 (66.75, 59.75) -> (66.75, 53.65)
  line L3 (53.25, 59.75) -> (66.75, 59.75)
  line L4 (53.25, 53.65) -> (53.25, 59.75)
  point P2 (53.25, 53.65)
  point P3 (66.75, 53.65)
  point P4 (66.75, 59.75)
  dimension "d446" distance P2 P3 = 13.5
  dimension "d447" distance P3 P4 = 6.1
extrude "Extrude56" new body sketch "MODE nest profile" against normal blind 8 bodies "MODE nest"
combine "Combine7" bodies "Battery low fence", "Battery low fence (1)", "Battery low fence (2)", "Battery low fence (3)", "Battery insulated bed", "Strap lug", "Strap lug (1)", "Charger clear-area PCB seat"
work_plane "WorkPlane57" AlongDistance 28.3 ExtraOffset 0
sketch "Strap slot tent roof" plane through (28.3, 0, 0) normal (1, 0, 0) x axis (0, 0, -1)
  line L1 (20.4, 23) -> (20.4, 20)
  line L2 (18.8, 23) -> (20.4, 23)
  line L3 (17.3, 21.5) -> (18.8, 23)
  line L4 (18.8, 20) -> (17.3, 21.5)
  line L5 (20.4, 20) -> (18.8, 20)
extrude "Extrude57" cut sketch "Strap slot tent roof" along normal blind 4.2
work_plane "WorkPlane58" AlongDistance 89.9 ExtraOffset 0
sketch "Strap slot tent roof (1)" plane through (89.9, 0, 0) normal (1, 0, 0) x axis (0, 0, -1)
  line L1 (20.4, 23) -> (20.4, 20)
  line L2 (18.8, 23) -> (20.4, 23)
  line L3 (17.3, 21.5) -> (18.8, 23)
  line L4 (18.8, 20) -> (17.3, 21.5)
  line L5 (20.4, 20) -> (18.8, 20)
extrude "Extrude58" cut sketch "Strap slot tent roof (1)" along normal blind 4.2
work_plane "WorkPlane59" AlongDistance -9.48 ExtraOffset 0
sketch "Charger USB front-loading top aperture profile" plane through (0, 0, -9.48) normal (0, 0, 1) x axis (1, 0, 0)
  line L1 (25.225, 57.35) -> (15.775, 57.35)
  line L2 (25.225, 60.15) -> (25.225, 57.35)
  line L3 (15.775, 60.15) -> (25.225, 60.15)
  line L4 (15.775, 57.35) -> (15.775, 60.15)
  point P2 (15.775, 57.35)
  point P3 (25.225, 57.35)
  point P4 (25.225, 60.15)
  dimension "d460" distance P2 P3 = 9.45
  dimension "d461" distance P3 P4 = 2.8
extrude "Extrude59" cut sketch "Charger USB front-loading top aperture profile" against normal blind 10.22
work_plane "WorkPlane60" AlongDistance -9.48 ExtraOffset 0
sketch "XIAO USB front-loading top aperture profile" plane through (0, 0, -9.48) normal (0, 0, 1) x axis (1, 0, 0)
  line L1 (102.685, 57.35) -> (93.115, 57.35)
  line L2 (102.685, 60.15) -> (102.685, 57.35)
  line L3 (93.115, 60.15) -> (102.685, 60.15)
  line L4 (93.115, 57.35) -> (93.115, 60.15)
  point P2 (93.115, 57.35)
  point P3 (102.685, 57.35)
  point P4 (102.685, 60.15)
  dimension "d466" distance P2 P3 = 9.57
  dimension "d467" distance P3 P4 = 2.8
extrude "Extrude60" cut sketch "XIAO USB front-loading top aperture profile" against normal blind 9.32
work_plane "WorkPlane61" AlongDistance -9.48 ExtraOffset 0
sketch "POWER body fit profile" plane through (0, 0, -9.48) normal (0, 0, 1) x axis (1, 0, 0)
  line L1 (46.5, 53.15) -> (35.5, 53.15)
  line L2 (46.5, 58.6) -> (46.5, 53.15)
  line L3 (35.5, 58.6) -> (46.5, 58.6)
  line L4 (35.5, 53.15) -> (35.5, 58.6)
  point P2 (35.5, 53.15)
  point P3 (46.5, 53.15)
  point P4 (46.5, 58.6)
  dimension "d472" distance P2 P3 = 11
  dimension "d473" distance P3 P4 = 5.45
extrude "Extrude61" cut sketch "POWER body fit profile" against normal blind 10.77
work_plane "WorkPlane62" AlongDistance -9.48 ExtraOffset 0
sketch "POWER mounting flange fit profile" plane through (0, 0, -9.48) normal (0, 0, 1) x axis (1, 0, 0)
  line L1 (51.065, 57.65) -> (30.935, 57.65)
  line L2 (51.065, 58.6) -> (51.065, 57.65)
  line L3 (30.935, 58.6) -> (51.065, 58.6)
  line L4 (30.935, 57.65) -> (30.935, 58.6)
  point P2 (30.935, 57.65)
  point P3 (51.065, 57.65)
  point P4 (51.065, 58.6)
  dimension "d478" distance P2 P3 = 20.13
  dimension "d479" distance P3 P4 = 0.95
extrude "Extrude62" cut sketch "POWER mounting flange fit profile" against normal blind 10.77
work_plane "WorkPlane63" AlongDistance -13.9 ExtraOffset 0
sketch "POWER three solder terminals bay profile" plane through (0, 0, -13.9) normal (0, 0, 1) x axis (1, 0, 0)
  line L1 (46.1, 48.25) -> (35.9, 48.25)
  line L2 (46.1, 53.35) -> (46.1, 48.25)
  line L3 (35.9, 53.35) -> (46.1, 53.35)
  line L4 (35.9, 48.25) -> (35.9, 53.35)
  point P2 (35.9, 48.25)
  point P3 (46.1, 48.25)
  point P4 (46.1, 53.35)
  dimension "d484" distance P2 P3 = 10.2
  dimension "d485" distance P3 P4 = 5.1
extrude "Extrude63" cut sketch "POWER three solder terminals bay profile" against normal blind 6.6
work_plane "WorkPlane64" AlongDistance -9.48 ExtraOffset 0
sketch "POWER direct lever top aperture profile" plane through (0, 0, -9.48) normal (0, 0, 1) x axis (1, 0, 0)
  line L1 (44.15, 58.4) -> (37.85, 58.4)
  line L2 (44.15, 60.2) -> (44.15, 58.4)
  line L3 (37.85, 60.2) -> (44.15, 60.2)
  line L4 (37.85, 58.4) -> (37.85, 60.2)
  point P2 (37.85, 58.4)
  point P3 (44.15, 58.4)
  point P4 (44.15, 60.2)
  dimension "d490" distance P2 P3 = 6.3
  dimension "d491" distance P3 P4 = 1.8
extrude "Extrude64" cut sketch "POWER direct lever top aperture profile" against normal blind 9.295
work_plane "WorkPlane65" AlongDistance -9.48 ExtraOffset 0
sketch "MODE body pocket 0.20 per side profile" plane through (0, 0, -9.48) normal (0, 0, 1) x axis (1, 0, 0)
  line L1 (64.75, 55.29) -> (55.25, 55.29)
  line L2 (64.75, 59.05) -> (64.75, 55.29)
  line L3 (55.25, 59.05) -> (64.75, 59.05)
  line L4 (55.25, 55.29) -> (55.25, 59.05)
  point P2 (55.25, 55.29)
  point P3 (64.75, 55.29)
  point P4 (64.75, 59.05)
  dimension "d496" distance P2 P3 = 9.5
  dimension "d497" distance P3 P4 = 3.76
extrude "Extrude65" cut sketch "MODE body pocket 0.20 per side profile" against normal blind 8.34
work_plane "WorkPlane66" AlongDistance -13.3 ExtraOffset 0
sketch "MODE lower solder bay profile" plane through (0, 0, -13.3) normal (0, 0, 1) x axis (1, 0, 0)
  line L1 (64.9, 48.9) -> (55.1, 48.9)
  line L2 (64.9, 53.65) -> (64.9, 48.9)
  line L3 (55.1, 53.65) -> (64.9, 53.65)
  line L4 (55.1, 48.9) -> (55.1, 53.65)
  point P2 (55.1, 48.9)
  point P3 (64.9, 48.9)
  point P4 (64.9, 53.65)
  dimension "d502" distance P2 P3 = 9.8
  dimension "d503" distance P3 P4 = 4.75
work_plane "WorkPlane67" AlongDistance -13.9 ExtraOffset 0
